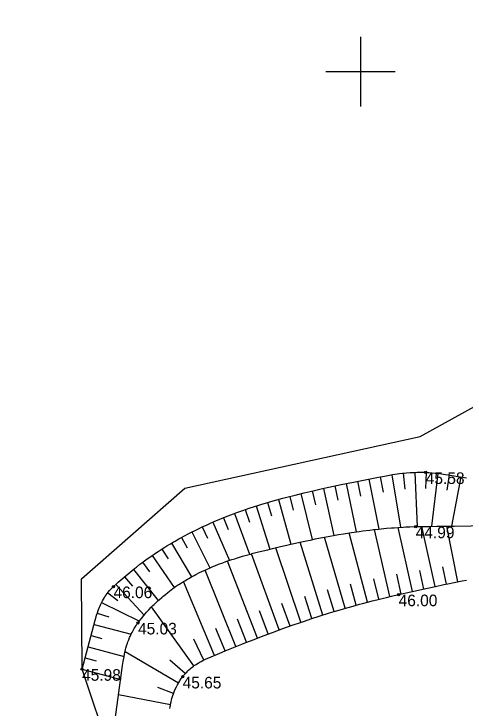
# Model space of a CAD drawing. Extents: x 561134 to 561329, y 413819 to 414116.
# Drawn here: x 561185.04 to 561204.52, y 413922.54 to 413952.49 of the extents above; entities that cross this region are included whole.
import ezdxf

# ---------------------------------------------------------------- set-up
doc = ezdxf.new("R2010")
doc.units = 0
for name, color, linetype in [('GEOD_ELEM_####_####_#', 7, 'Continuous'), ('RAMI_UZMR_####_####_#', 7, 'Continuous'), ('RELJ_AATZ_####_TKST_#', 7, 'Continuous'), ('RELJ_ELEM_####_####_#', 7, 'Continuous'), ('RELJ_NOGA_####_####_#', 7, 'Continuous'), ('RELJ_NOGL_####_####_#', 7, 'Continuous')]:
    doc.layers.add(name, color=color, linetype=linetype)

msp = doc.modelspace()

# ---------------------------------------------------------------- linework, layer by layer
at = {"layer": 'GEOD_ELEM_####_####_#'}
for p, q in [((561200, 413951.5), (561200, 413950)), ((561198.5, 413950), (561200, 413950)), ((561200, 413950), (561200, 413948.5)), ((561200, 413950), (561201.5, 413950))]:
    msp.add_line(p, q, dxfattribs=at)
at = {"layer": 'RAMI_UZMR_####_####_#'}
msp.add_lwpolyline([(561188.512, 413892.082), (561185.041, 413910.753), (561191.104, 413917.736), (561189.205, 413920.568), (561187.984, 413924.22), (561187.954, 413928.121), (561192.417, 413932.029), (561202.582, 413934.262), (561206.983, 413936.681), (561215.453, 413945.229), (561216.519, 413946.905), (561218.27, 413950.393), (561229.69, 413964.77), (561237.253, 413982.653), (561235.655, 414013.737)], dxfattribs=at)
at = {"layer": 'RELJ_ELEM_####_####_#'}
for centre in [(561202.819, 413932.709), (561202.384, 413930.368), (561189.34, 413927.784), (561201.647, 413927.435), (561190.399, 413926.218), (561187.984, 413924.22), (561192.324, 413923.889)]:
    msp.add_circle(centre, 0.05, dxfattribs=at)
at = {"layer": 'RELJ_NOGA_####_####_#'}
for p, q in [((561201.347, 413932.605), (561201.722, 413930.34)), ((561201.842, 413932.673), (561201.917, 413931.979)), ((561202.341, 413932.711), (561202.443, 413930.369)), ((561202.84, 413932.708), (561202.8, 413932.008)), ((561203.339, 413932.666), (561203.065, 413930.382)), ((561203.834, 413932.598), (561203.726, 413931.935)), ((561199.873, 413932.324), (561200, 413931.689)), ((561200.364, 413932.421), (561200.789, 413930.264)), ((561200.855, 413932.517), (561200.981, 413931.855)), ((561204.327, 413932.513), (561203.932, 413930.395)), ((561198.405, 413932.018), (561198.847, 413929.988)), ((561198.894, 413932.123), (561199.024, 413931.507)), ((561199.383, 413932.225), (561199.808, 413930.143)), ((561196.946, 413931.672), (561197.097, 413931.083)), ((561197.431, 413931.793), (561197.917, 413929.809)), ((561197.917, 413931.909), (561198.056, 413931.306)), ((561195.982, 413931.406), (561196.153, 413930.836)), ((561196.463, 413931.543), (561196.992, 413929.608)), ((561195.029, 413931.102), (561195.216, 413930.558)), ((561195.504, 413931.259), (561196.094, 413929.397)), ((561194.558, 413930.934), (561195.212, 413929.174)), ((561193.63, 413930.563), (561194.348, 413928.912)), ((561194.091, 413930.755), (561194.294, 413930.242)), ((561193.174, 413930.358), (561193.396, 413929.877)), ((561201.273, 413927.35), (561200.599, 413930.244)), ((561202.249, 413927.569), (561201.629, 413930.335)), ((561203.225, 413927.787), (561202.654, 413930.374)), ((561204.204, 413927.991), (561203.733, 413930.392)), ((561192.282, 413929.906), (561192.527, 413929.455)), ((561192.724, 413930.139), (561193.501, 413928.589)), ((561199.338, 413926.846), (561198.449, 413929.914)), ((561200.302, 413927.111), (561199.516, 413930.099)), ((561191.847, 413929.658), (561192.707, 413928.202)), ((561198.381, 413926.556), (561197.395, 413929.698)), ((561191.421, 413929.397), (561191.695, 413928.973)), ((561197.431, 413926.244), (561196.341, 413929.456)), ((561191.005, 413929.121), (561191.961, 413927.737)), ((561196.488, 413925.911), (561195.294, 413929.196)), ((561190.598, 413928.83), (561190.898, 413928.42)), ((561195.551, 413925.56), (561194.267, 413928.885)), ((561190.201, 413928.526), (561191.271, 413927.182)), ((561194.621, 413925.193), (561193.292, 413928.496)), ((561202.737, 413927.678), (561202.556, 413928.483)), ((561203.714, 413927.892), (561203.556, 413928.639)), ((561189.815, 413928.208), (561190.155, 413927.805)), ((561200.787, 413927.234), (561200.571, 413928.118)), ((561201.761, 413927.46), (561201.571, 413928.311)), ((561189.441, 413927.877), (561190.663, 413926.55)), ((561193.697, 413924.812), (561192.358, 413927.999)), ((561199.819, 413926.982), (561199.569, 413927.891)), ((561189.094, 413927.517), (561189.526, 413927.179)), ((561198.858, 413926.704), (561198.574, 413927.635)), ((561197.905, 413926.403), (561197.595, 413927.356)), ((561188.828, 413927.095), (561190.458, 413926.296)), ((561192.808, 413924.359), (561190.987, 413926.906)), ((561196.959, 413926.08), (561196.612, 413927.054)), ((561188.639, 413926.632), (561189.142, 413926.472)), ((561196.019, 413925.738), (561195.647, 413926.731)), ((561195.086, 413925.379), (561194.695, 413926.377)), ((561188.502, 413926.152), (561190.099, 413925.724)), ((561194.158, 413925.004), (561193.754, 413925.981)), ((561188.372, 413925.669), (561188.836, 413925.545)), ((561193.239, 413924.612), (561192.802, 413925.511)), ((561188.243, 413925.186), (561189.798, 413924.769)), ((561192.146, 413923.62), (561189.84, 413924.968)), ((561188.113, 413924.703), (561188.595, 413924.574)), ((561192.436, 413924.027), (561191.777, 413924.613)), ((561187.984, 413924.22), (561189.65, 413923.773)), ((561191.933, 413923.169), (561191.258, 413923.424)), ((561191.801, 413922.687), (561189.558, 413923.108))]:
    msp.add_line(p, q, dxfattribs=at)
for points in [[(561187.984, 413924.22), (561188.551, 413926.336), (561188.59, 413926.475), (561188.611, 413926.544), (561188.644, 413926.646), (561188.679, 413926.748), (561188.698, 413926.798), (561188.737, 413926.898), (561188.758, 413926.947), (561188.791, 413927.021), (561188.839, 413927.117), (561188.864, 413927.165), (561188.903, 413927.236), (561188.946, 413927.306), (561188.968, 413927.341), (561189.009, 413927.402), (561189.03, 413927.432), (561189.063, 413927.477), (561189.115, 413927.544), (561189.171, 413927.609), (561189.2, 413927.642), (561189.26, 413927.706), (561189.291, 413927.737), (561189.34, 413927.784), (561189.465, 413927.899), (561189.548, 413927.974), (561189.716, 413928.123), (561189.8, 413928.195), (561189.97, 413928.338), (561190.14, 413928.477), (561190.254, 413928.568), (561190.33, 413928.627), (561190.483, 413928.745), (561190.569, 413928.809), (561190.743, 413928.936), (561190.917, 413929.06), (561191.034, 413929.141), (561191.112, 413929.194), (561191.268, 413929.298), (561191.445, 413929.412), (561191.563, 413929.486), (561191.642, 413929.535), (561191.801, 413929.631), (561191.921, 413929.702), (561192, 413929.748), (561192.16, 413929.839), (561192.241, 413929.883), (561192.402, 413929.971), (561192.563, 413930.056), (561192.672, 413930.112), (561192.888, 413930.221), (561192.98, 413930.266), (561193.164, 413930.353), (561193.349, 413930.439), (561193.473, 413930.494), (561193.721, 413930.602), (561193.908, 413930.681), (561194.033, 413930.732), (561194.284, 413930.831), (561194.41, 413930.879), (561194.663, 413930.973), (561194.916, 413931.064), (561195.086, 413931.122), (561195.199, 413931.16), (561195.427, 413931.235), (561195.619, 413931.296), (561195.748, 413931.335), (561196.005, 413931.413), (561196.135, 413931.451), (561196.394, 413931.524), (561196.654, 413931.595), (561196.828, 413931.642), (561197.177, 413931.731), (561197.571, 413931.828), (561197.834, 413931.89), (561198.01, 413931.93), (561198.363, 413932.009), (561198.629, 413932.067), (561199.162, 413932.18), (561199.697, 413932.289), (561200.055, 413932.36), (561200.773, 413932.502), (561201.043, 413932.553), (561201.177, 413932.577), (561201.38, 413932.611), (561201.582, 413932.641), (561201.683, 413932.654), (561201.818, 413932.67), (561201.886, 413932.678), (561201.987, 413932.688), (561202.139, 413932.7), (561202.273, 413932.708), (561202.341, 413932.711), (561202.442, 413932.714), (561202.593, 413932.715), (561202.744, 413932.712), (561202.819, 413932.709), (561202.954, 413932.701), (561203.044, 413932.695), (561203.224, 413932.678), (561203.314, 413932.669), (561203.494, 413932.647), (561203.674, 413932.623), (561203.794, 413932.605), (561204.033, 413932.566), (561204.213, 413932.534), (561204.573, 413932.467)], [(561191.774, 413922.522), (561191.787, 413922.607), (561191.794, 413922.65), (561191.806, 413922.713), (561191.826, 413922.807), (561191.849, 413922.9), (561191.861, 413922.947), (561191.888, 413923.039), (561191.903, 413923.084), (561191.927, 413923.153), (561191.961, 413923.243), (561191.979, 413923.288), (561192.008, 413923.355), (561192.055, 413923.454), (561192.101, 413923.542), (561192.125, 413923.585), (561192.163, 413923.65), (561192.203, 413923.714), (561192.224, 413923.746), (561192.267, 413923.81), (561192.289, 413923.842), (561192.324, 413923.889), (561192.358, 413923.933), (561192.381, 413923.962), (561192.428, 413924.017), (561192.452, 413924.044), (561192.5, 413924.096), (561192.55, 413924.146), (561192.584, 413924.178), (561192.654, 413924.239), (561192.68, 413924.262), (561192.734, 413924.305), (561192.789, 413924.346), (561192.826, 413924.373), (561192.902, 413924.424), (561192.96, 413924.46), (561192.999, 413924.484), (561193.079, 413924.529), (561193.119, 413924.551), (561193.201, 413924.594), (561193.284, 413924.634), (561193.34, 413924.66), (561193.454, 413924.71), (561193.928, 413924.909), (561194.164, 413925.007), (561194.519, 413925.152), (561194.874, 413925.295), (561195.051, 413925.365), (561195.406, 413925.504), (561195.583, 413925.573), (561195.85, 413925.674), (561196.205, 413925.807), (561196.383, 413925.873), (561196.65, 413925.97), (561197.051, 413926.112), (561197.408, 413926.236), (561197.586, 413926.297), (561197.855, 413926.386), (561198.258, 413926.517), (561198.663, 413926.644), (561198.866, 413926.706), (561199.228, 413926.814), (561199.409, 413926.866), (561199.681, 413926.944), (561199.955, 413927.019), (561200.092, 413927.056), (561200.366, 413927.128), (561200.504, 413927.163), (561200.71, 413927.215), (561200.987, 413927.283), (561201.125, 413927.316), (561201.333, 413927.365), (561201.647, 413927.435), (561202.179, 413927.553), (561202.887, 413927.712), (561203.241, 413927.79), (561203.596, 413927.867), (561203.773, 413927.904), (561204.039, 413927.959), (561204.393, 413928.028), (561204.571, 413928.061)]]:
    msp.add_lwpolyline(points, dxfattribs=at)
at = {"layer": 'RELJ_NOGL_####_####_#'}
msp.add_lwpolyline([(561189.205, 413920.568), (561189.733, 413924.374), (561189.758, 413924.544), (561189.772, 413924.628), (561189.795, 413924.754), (561189.82, 413924.879), (561189.833, 413924.942), (561189.863, 413925.065), (561189.879, 413925.127), (561189.905, 413925.219), (561189.944, 413925.341), (561189.965, 413925.401), (561189.998, 413925.492), (561190.035, 413925.582), (561190.054, 413925.626), (561190.09, 413925.706), (561190.109, 413925.745), (561190.139, 413925.804), (561190.187, 413925.892), (561190.238, 413925.98), (561190.265, 413926.024), (561190.322, 413926.11), (561190.352, 413926.154), (561190.399, 413926.218), (561190.449, 413926.284), (561190.549, 413926.412), (561190.652, 413926.537), (561190.722, 413926.618), (561190.768, 413926.672), (561190.863, 413926.776), (561190.972, 413926.891), (561191.045, 413926.965), (561191.094, 413927.014), (561191.194, 413927.11), (561191.269, 413927.18), (561191.32, 413927.226), (561191.423, 413927.316), (561191.475, 413927.361), (561191.579, 413927.447), (561191.685, 413927.532), (561191.756, 413927.587), (561191.9, 413927.693), (561192.023, 413927.781), (561192.106, 413927.837), (561192.162, 413927.874), (561192.274, 413927.947), (561192.359, 413928), (561192.416, 413928.034), (561192.53, 413928.102), (561192.588, 413928.136), (561192.703, 413928.201), (561192.82, 413928.264), (561192.899, 413928.305), (561193.057, 413928.385), (561193.146, 413928.428), (561193.327, 413928.512), (561193.509, 413928.593), (561193.631, 413928.644), (561193.713, 413928.678), (561193.878, 413928.743), (561194.065, 413928.813), (561194.191, 413928.858), (561194.275, 413928.887), (561194.443, 413928.944), (561194.571, 413928.985), (561194.656, 413929.012), (561194.826, 413929.064), (561194.912, 413929.09), (561195.084, 413929.139), (561195.256, 413929.186), (561195.372, 413929.217), (561195.603, 413929.276), (561195.998, 413929.374), (561196.196, 413929.422), (561196.493, 413929.492), (561196.937, 413929.596), (561197.382, 413929.695), (561197.604, 413929.743), (561197.9, 413929.806), (561198.048, 413929.836), (561198.271, 413929.88), (561198.605, 413929.944), (561198.901, 413929.998), (561199.05, 413930.023), (561199.273, 413930.061), (561199.607, 413930.113), (561199.942, 413930.162), (561200.109, 413930.185), (561200.408, 413930.222), (561200.557, 413930.239), (561200.781, 413930.264), (561201.005, 413930.286), (561201.117, 413930.296), (561201.342, 413930.314), (561201.454, 413930.323), (561201.623, 413930.334), (561201.848, 413930.347), (561201.961, 413930.353), (561202.13, 413930.36), (561202.384, 413930.368), (561202.935, 413930.38), (561203.303, 413930.386), (561204.038, 413930.396), (561205.508, 413930.412)], dxfattribs=at)

# ---------------------------------------------------------------- texts
at = {"layer": 'RELJ_AATZ_####_TKST_#'}
for s, p in [('45.58', (561202.819, 413932.209)), ('44.99', (561202.384, 413929.868)), ('46.06', (561189.34, 413927.284)), ('46.00', (561201.647, 413926.935)), ('45.03', (561190.399, 413925.718)), ('45.98', (561187.984, 413923.72)), ('45.65', (561192.324, 413923.389))]:
    msp.add_text(s, height=0.5, dxfattribs=at).set_placement(p)

doc.saveas('drawing.dxf')
